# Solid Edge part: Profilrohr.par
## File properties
Username: bmolnar
Dokumentum tartalom típus: 0
Author: bmolnar
Last saved by: bmolnar
Revision: 92
Sűrűség: 0,000 kg/m^3
Pontosság: 0,990
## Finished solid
Body 1: solid body, 115 faces, 338 edges, 224 vertices.
  Faces by surface: cylinder 59, plane 56
  Edges by curve: line 220, circle 118
Bounding box of the edges (mm): 113.500 x 113.500 x 228.000, from (-56.75, -56.75, -211.5) to (56.75, 56.75, 16.5).
Cylindrical faces by radius (mm): R0.15 x24, R0.25 x24, R1 x4, R12.25 x4, R35 x2, R50 x1
Planar faces by outward normal: +x 13, +y 14, +z 1, -x 13, -y 14, -z 1
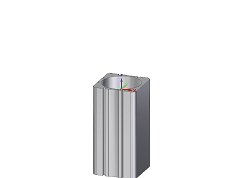
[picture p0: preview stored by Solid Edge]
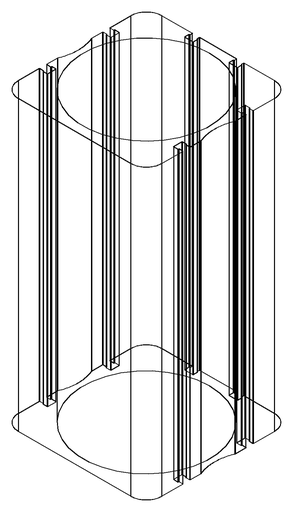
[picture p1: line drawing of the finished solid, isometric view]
